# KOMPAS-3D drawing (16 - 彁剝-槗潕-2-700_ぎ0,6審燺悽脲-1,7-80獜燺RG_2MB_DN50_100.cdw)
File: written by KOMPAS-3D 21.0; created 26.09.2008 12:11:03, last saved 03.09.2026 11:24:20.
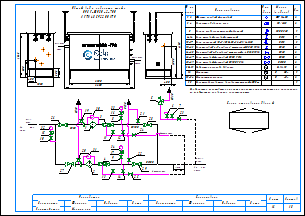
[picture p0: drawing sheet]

Sheets 1-2: A3, landscape

Document properties: Наименование: Макро:21; Автор: RaskoAdmin; Форматы листов документа: 2xA3; Полное имя файла: \\UR38nt01\Departments\КТО\КБ ПУРДГ\Заявки\Прайс-лист на типовые шкафы ГРПШ\ПРДГ_стандарт_20_03_2026\ПРДГ с RG_2MB\ПРДГ-ШУЭО-2-700_до0,6МПа_Рвых-1,7-80кПа_RG_2MB_DN50_100.cdw

Title block, sheet 1: Наименование: Пункт учета газа / ПУГ-Ш-400-Р / ЛГТИ.485922.001ТУ; designation: ЛГТИ.03.4411141; sheet number: 1; Количество листов документа: 2; organisation: ООО "ЭЛЬСТЕР Газэлектроника"; Форматы листов документа: A3; stored path: C:\Рабочие документы\Компас\ПУГ\Схема.cdw; Разработал: Устинов; Проверил: Кошкин; Утвердил: Кошкин
Title block, sheet 2: sheet number: 2; stored path: D:\Рабочие документы\Заявки\ПУРДГ\ПУРДГ-ШУЭО-2-100-Р 4411220.cdw; designation, second copy: ЛГТИ.03.4411141-

Views: Вид 1, Вид 2
Referenced files: wcvoit.frw
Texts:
  Normal
  Вход
  газа
  PDI
  Выход
  Р=     кПа
  DN100
  DN50
  DN20
  Импульс DN20
  ≥5DN
  HYSWLongFangSong
  № на
  схеме
  Усл.
  обозн.
  Марка
  (модель)
  Кол.
  Фильтр газовый фланцевый
  ФГ 16-50
  Регулятор давления газа
  RG/2MB
  Клапан предохранительный сбросной
  КПС DN20
  Кран шаровой газовый латунный
  DN15
  Кран кнопочный VE-РАСКО-НЗ-1,6-G1/2-М20
  Кран шаровой "под приварку" штуцерный DN20 PN16
  Кран шаровой "под приварку" штуцерный п/п DN20 PN16
  Кран шаровой фланцевый DN50 PN16
  Кран шаровой фланцевый DN100 PN16
  Индикатор перепада давления
  Delta 15
  Манометр
  Манометр-напоромер
  Электрообогреватель взрывозащищенный 400Вт
  0...     МПа
  0...     кПа
  Общий вид и габариты шкафа
  ПРДГ-ШУЭО-2-700
  Выход газа
  Вход газа
  Р=        МПа
  logo-rasko-ge.png
  Схема открывания дверей
  Предприятие изготовитель может заменять комплектующие на аналогичные,
  не ухудшающие заявленных характеристик.
  Должность
  Конструктор
  Фамилия
  Подпись
  Дата
  Согласовано
  Максимкин
  Лист
  Листов
  POLYLINE_STYLE_0.18_RGB_0_0_0
  POLYLINE_STYLE_0.50_RGB_0_0_0
  POLYLINE_STYLE_0.34_RGB_0_0_0
  PHANTOM_RGB_0_0_0_SC_1_THICK_0.18
  K5LT_THIN_RGB_0_0_0_THICK_0.18
  K5LT32769_RGB_0_0_0_THICK_0.18
  K5LT12_RGB_0_0_0_SC_1_THICK_0.18
  K5LT_DASHED_RGB_0_0_0_SC_1_THICK_0.18
  ACISOTGL_RGB_0_0_0_SC_0.8_THICK_0.25
  CONTINUOUS_RGB_0_127_31_THICK_0.3
  CONTINUOUS_RGB_0_0_255_THICK_0.35
  CONTINUOUS_RGB_255_0_0_THICK_0.35
  POLYLINE_STYLE_0.25_RGB_0_0_0
  CONTINUOUS_RGB_0_0_0_THICK_0.5
  POLYLINE_STYLE_0.35_RGB_0_0_255
  CONTINUOUS_RGB_0_0_0_THICK_0.4
  CONTINUOUS_RGB_0_0_0_THICK_0.35
  Без оформления
Dimensions and other numbers on the sheet: 1; 2; 3; 4; 5; 10; 27; 28; 29; 23; 8; 12; 19; 20; 21; 22; 25; 24; 30; 31; 15; 16; 26; 6; 7; 11; 14; 13; 33; 1, 2; 3, 4; 6-14; 9; 15-17; 18-23; 24-25; 26-27; 28-29; 30-31; 32; 33-34; 35; 400; 1050; 500; 305; 2300; 1565; 2600; 17; 34; 1000; 4130; 18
